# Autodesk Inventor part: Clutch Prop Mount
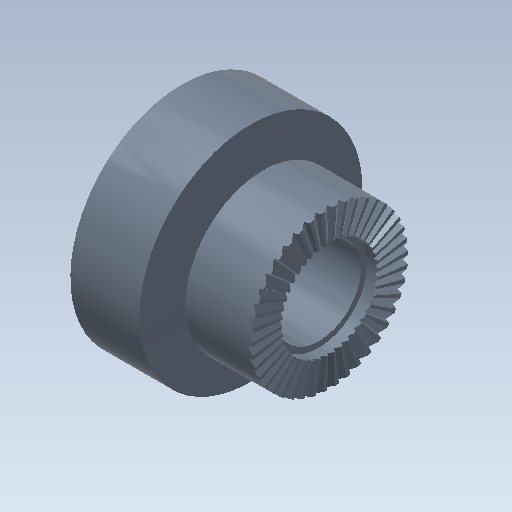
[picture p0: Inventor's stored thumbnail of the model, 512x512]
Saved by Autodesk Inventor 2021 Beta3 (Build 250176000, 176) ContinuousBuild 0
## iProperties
Created: 2012-08
Part Number: Clutch Prop Mount
Material: Stainless Steel, 440C
Document SubType Name: Modeling
Designer: John
Density: 7.75 g/cm^3
Mass: 13.9161 g
Surface Area: 27.6405 cm^2
Volume: 1.79562 cm^3
Appearance: Steel Blue
Author: John
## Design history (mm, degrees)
sketch "Sketch1"
  geometry: C1 r 12.509 at (0, 0); 1 further point
  constraints: 1 centre point, 1 coincident
  dimensions: "d0" = 25.019 diameter of C1
extrude "Extrusion1" new body sketch "Sketch1" distance "d1" = 7.747; taper "d2" = 0 deg
sketch "Sketch3"
  geometry: C1 r 12.509 at (0, 0) reference; C2 r 8.763 at (0, 0)
  constraints: 1 centre point, 1 coincident
  dimensions: "d3" = 17.526 diameter of C2
extrude "Extrusion2" join sketch "Sketch3" distance "d5" = 8.89; taper "d6" = 0 deg
sketch "Sketch4"
  geometry: C1 r 8.763 at (0, 0) reference; C2 r 6.782 at (0, 0)
  constraints: 1 centre point
  dimensions: "d26" = 6.7818 radius of C2
extrude "Extrusion3" cut sketch "Sketch4" distance "d8" = 1.397; taper "d9" = 0 deg
sketch "Sketch5"
  geometry: C1 r 8.763 at (0, 0) reference
hole "Hole1" sketch "Sketch5" at (0, 0) diameter "d10" = 9.525; stored, may be unused: countersink angle "d14" = 82 deg, drill point angle "d16" = 118 deg; dims "d11" = 19.05, "d12" = 9.525, "d13" = 6.35, "d15" = 25.4
sketch "Sketch6"
  geometry: C1 r 4.763 at (0, 0) reference
hole "Hole2" sketch "Sketch6" at (0, 0) diameter "d17" = 23.114; stored, may be unused: countersink angle "d21" = 82 deg, drill point angle "d23" = 0 deg; dims "d18" = 19.05, "d19" = 9.525, "d20" = 6.35, "d22" = 6.8072
sketch "Sketch10"
  geometry: L1 (-16.637, -4.763)-(-16.637, 4.763) reference; L2 (0, 0)-(-16.637, 0); L3 (-16.637, 0.009)-(-16.612, 0); L4 (-16.612, 0)-(-16.637, -0.036)
  constraints: 6 end point, 3 point on line, 1 midpoint
  dimensions: "d34" = 75 deg angle of L4 L3; "d35" = 0.0254 distance from line of L1 L3.end
extrude "Extrusion6" cut sketch "Sketch10" extent not by distance; stored distance "d36" = 1.27; taper "d37" = 2 deg
sketch "Sketch11"
  geometry: C1 r 5.397 at (0, 0); A1 r 8.763 centre (0, 0) between (0.57, -8.744) and (0.974, -8.709) reference
  constraints: 1 centre point, 1 coincident
  dimensions: "d42" = 10.795 diameter of C1
extrude "Extrusion7" cut sketch "Sketch11" distance "d43" = 1.27; taper "d44" = 0 deg
body "Solid1"
pattern_circular "Circular Pattern1" dims angle "d40" = 360 deg
